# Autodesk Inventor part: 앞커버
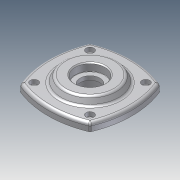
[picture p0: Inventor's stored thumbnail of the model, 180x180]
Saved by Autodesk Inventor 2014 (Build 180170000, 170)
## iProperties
Created: 2013-02
Part Number: 앞커버
Document SubType Name: Modeling
Designer: 한국산업디자인학원[gmhk.co.kr]
Density: 1 g/cm^3
Material: 일반
Appearance: 기본값
Mass: 76.2425 g
Surface Area: 198.108 cm^2
Volume: 76.2425 cm^3
Author: 한국산업디자인학원[gmhk.co.kr]
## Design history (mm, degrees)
sketch "스케치1"
  geometry: C1 r 30 at (0, 0) reference; A1 r 91.05 centre (0, -48.55) between (34.185, 35.839) and (-34.185, 35.839) reference; A2 r 91.05 centre (48.55, 0) between (-35.839, 34.185) and (-35.839, -34.185) reference; A3 r 3 centre (-33.058, 33.058) between (-34.185, 35.839) and (-35.839, 34.185) reference; A4 r 3 centre (33.058, 33.058) between (35.839, 34.185) and (34.185, 35.839) reference; A5 r 91.05 centre (-48.55, 0) between (35.839, -34.185) and (35.839, 34.185) reference; A6 r 3 centre (33.058, -33.058) between (34.185, -35.839) and (35.839, -34.185) reference; A7 r 91.05 centre (0, 48.55) between (-34.185, -35.839) and (34.185, -35.839) reference; A8 r 3 centre (-33.058, -33.058) between (-35.839, -34.185) and (-34.185, -35.839) reference; 1 further point
  node "참조1"
  node "참조2"
  node "참조3"
  node "참조4"
  node "참조5"
  node "참조6"
  node "참조7"
  node "참조8"
  node "참조9"
extrude "돌출1" new body sketch "스케치1" distance "d0" = 8; taper "d1" = 0 deg
sketch "스케치2"
  geometry: C1 r 30 at (0, 0); 1 further point
  constraints: 1 centre point, 1 coincident
  dimensions: "d2" = 60 diameter of C1
extrude "돌출2" join sketch "스케치2" distance "d3" = 7; taper "d4" = -30 deg
hole "구멍1" diameter "d7" = 20; stored, may be unused: countersink angle "d11" = 90 deg, drill point angle "d13" = 118 deg; dims "d5" = 10, "d6" = 10, "d8" = 6, "d9" = 30, "d10" = 8, "d12" = 20
sketch "스케치3"
  geometry: C1 r 1.621 at (28.284, 28.284) reference; C2 r 1.621 at (-28.284, 28.284) reference; C3 r 1.621 at (-28.284, -28.284) reference; C4 r 1.621 at (28.284, -28.284) reference; 1 further point
hole "구멍2" sketch "스케치3" at (28.284, 28.284), (28.284, -28.284), (-28.284, -28.284), (-28.284, 28.284) diameter "d14" = 4.5; stored, may be unused: countersink angle "d18" = 90 deg, drill point angle "d20" = 118 deg; dims "d15" = 6, "d16" = 8, "d17" = 4.4, "d19" = 20
extrude "돌출3" join sketch "스케치1" distance "d21" = 12; taper "d22" = 0 deg
hole "구멍3" diameter "d25" = 30; stored, may be unused: countersink angle "d29" = 90 deg, drill point angle "d31" = 0 deg; dims "d23" = 10, "d24" = 10, "d26" = 6, "d27" = 40, "d28" = 12, "d30" = 15
fillet "모깎기1" dims "d32" = 3, "d33" = 0.3
chamfer "모따기1" distance "d34" = 1; stored, may be unused: second distance "d35" = 2, angle "d36" = 45 deg
node "솔리드1"
node "참조10"
node "참조11"
node "참조12"
node "참조13"
